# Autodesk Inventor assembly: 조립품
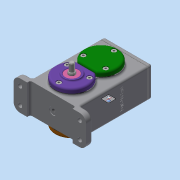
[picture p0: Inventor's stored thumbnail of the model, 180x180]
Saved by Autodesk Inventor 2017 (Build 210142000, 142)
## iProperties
Part Number: 조립품
Material: 일반
Document SubType Name: Assembly
Designer: 222
Author: 222
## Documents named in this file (24)
- C:\Users\222\Desktop\600506V1058\조립품.iam
- C:\Users\222\Desktop\600506V1058\본체.ipt
- C:\Users\222\Desktop\600506V1058\Ű 4 x 4 x 12.ipt
- C:\Users\222\Desktop\600506V1058\Ű 5 x 5 x 12.ipt
- C:\Users\222\Desktop\600506V1058\개스킷 A.ipt
- C:\Users\222\Desktop\600506V1058\개스킷 B.ipt
- C:\Users\222\Desktop\600506V1058\개스킷 C.ipt
- C:\Users\222\Desktop\600506V1058\베어링 6001.ipt
- 베어링 6001.ipt
- C:\Users\222\Desktop\600506V1058\베어링 6002.ipt
- 베어링 6002.ipt
- C:\Users\222\Desktop\600506V1058\볼트 M4.ipt
- C:\Users\222\Desktop\600506V1058\스퍼기어 A.ipt
- C:\Users\222\Desktop\600506V1058\스퍼기어 B.ipt
- C:\Users\222\Desktop\600506V1058\오일 실 10 20 7.ipt
- C:\Users\222\Desktop\600506V1058\오일 실 12 22 7.ipt
- C:\Users\222\Desktop\600506V1058\축 A.ipt
- C:\Users\222\Desktop\600506V1058\축 B.ipt
- C:\Users\222\Desktop\600506V1058\칼라.ipt
- C:\Users\222\Desktop\600506V1058\커버 A.ipt
- C:\Users\222\Desktop\600506V1058\커버 B.ipt
- C:\Users\222\Desktop\600506V1058\커버 C.ipt
- C:\Users\222\Desktop\600506V1058\커버 D.ipt
- C:\Users\222\Desktop\600506V1058\커버 E.ipt
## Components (7 placed, 5 different names)
1. Ű 4 x 4 x 12:1
2. Ű 5 x 5 x 12:1
3. 개스킷 A:1
4. 개스킷 B:1
5. 개스킷 C:1
6. 개스킷 B:2
7. 개스킷 B:3
